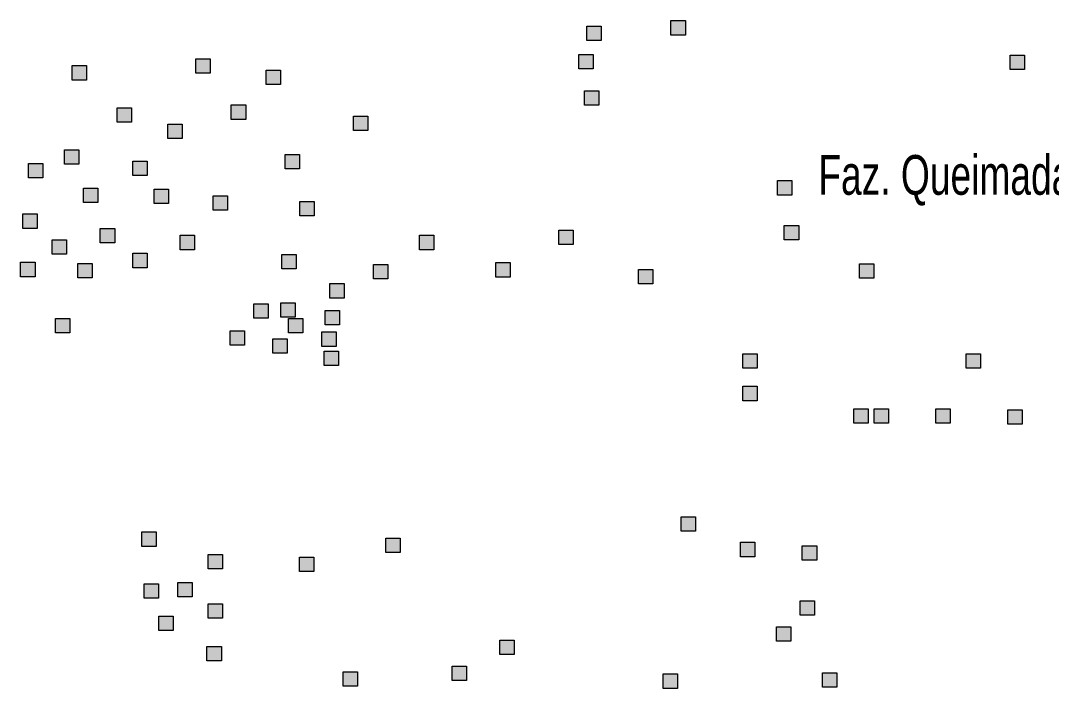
# Model space of a CAD drawing. Extents: x 445.4 to 500, y 8728.7 to 8784.
# Drawn here: x 467.932 to 472.087, y 8728.719 to 8731.409 of the extents above; entities that cross this region are included whole.
import ezdxf

# ---------------------------------------------------------------- set-up
doc = ezdxf.new("R2010")
doc.units = 0
doc.header["$LTSCALE"] = 0.064
doc.layers.add('2', color=7, linetype='Continuous', lineweight=25)
doc.layers.add('61', color=7, linetype='Continuous')

msp = doc.modelspace()

# ---------------------------------------------------------------- hatches: boundary and pattern name
at = {"layer": '2'}
for points in [[(470.5532, 8731.409), (470.6112, 8731.409), (470.6112, 8731.351), (470.5532, 8731.351)], [(470.2138, 8731.3864), (470.2718, 8731.3864), (470.2718, 8731.3284), (470.2138, 8731.3284)], [(470.1821, 8731.2732), (470.2401, 8731.2732), (470.2401, 8731.2152), (470.1821, 8731.2152)], [(468.6377, 8731.2549), (468.6957, 8731.2549), (468.6957, 8731.1969), (468.6377, 8731.1969)], [(471.9206, 8731.2699), (471.9786, 8731.2699), (471.9786, 8731.2119), (471.9206, 8731.2119)], [(468.1399, 8731.2277), (468.1979, 8731.2277), (468.1979, 8731.1697), (468.1399, 8731.1697)], [(468.9214, 8731.2096), (468.9794, 8731.2096), (468.9794, 8731.1516), (468.9214, 8731.1516)], [(470.2047, 8731.1266), (470.2627, 8731.1266), (470.2627, 8731.0686), (470.2047, 8731.0686)], [(468.7811, 8731.0693), (468.8391, 8731.0693), (468.8391, 8731.0113), (468.7811, 8731.0113)], [(468.3209, 8731.0573), (468.3789, 8731.0573), (468.3789, 8730.9993), (468.3209, 8730.9993)], [(469.273, 8731.024), (469.331, 8731.024), (469.331, 8730.966), (469.273, 8730.966)], [(468.5246, 8730.9923), (468.5826, 8730.9923), (468.5826, 8730.9343), (468.5246, 8730.9343)], [(468.1083, 8730.8882), (468.1663, 8730.8882), (468.1663, 8730.8302), (468.1083, 8730.8302)], [(468.9983, 8730.8701), (469.0563, 8730.8701), (469.0563, 8730.8121), (468.9983, 8730.8121)], [(467.9635, 8730.8339), (468.0215, 8730.8339), (468.0215, 8730.7759), (467.9635, 8730.7759)], [(468.3843, 8730.8429), (468.4423, 8730.8429), (468.4423, 8730.7849), (468.3843, 8730.7849)], [(468.1852, 8730.7342), (468.2432, 8730.7342), (468.2432, 8730.6762), (468.1852, 8730.6762)], [(470.983, 8730.7644), (471.041, 8730.7644), (471.041, 8730.7064), (470.983, 8730.7064)], [(468.4703, 8730.7297), (468.5283, 8730.7297), (468.5283, 8730.6717), (468.4703, 8730.6717)], [(468.7075, 8730.7038), (468.7655, 8730.7038), (468.7655, 8730.6458), (468.7075, 8730.6458)], [(469.0571, 8730.6799), (469.1151, 8730.6799), (469.1151, 8730.6219), (469.0571, 8730.6219)], [(467.9408, 8730.6301), (467.9988, 8730.6301), (467.9988, 8730.5721), (467.9408, 8730.5721)], [(468.2531, 8730.5713), (468.3111, 8730.5713), (468.3111, 8730.5133), (468.2531, 8730.5133)], [(471.0102, 8730.5833), (471.0682, 8730.5833), (471.0682, 8730.5253), (471.0102, 8730.5253)], [(468.0585, 8730.526), (468.1165, 8730.526), (468.1165, 8730.468), (468.0585, 8730.468)], [(468.5743, 8730.5441), (468.6323, 8730.5441), (468.6323, 8730.4861), (468.5743, 8730.4861)], [(469.5399, 8730.5441), (469.5979, 8730.5441), (469.5979, 8730.4861), (469.5399, 8730.4861)], [(470.1007, 8730.5652), (470.1587, 8730.5652), (470.1587, 8730.5072), (470.1007, 8730.5072)], [(468.3843, 8730.4717), (468.4423, 8730.4717), (468.4423, 8730.4137), (468.3843, 8730.4137)], [(468.9847, 8730.4671), (469.0427, 8730.4671), (469.0427, 8730.4091), (468.9847, 8730.4091)], [(467.9318, 8730.4354), (467.9898, 8730.4354), (467.9898, 8730.3774), (467.9318, 8730.3774)], [(468.1626, 8730.4309), (468.2206, 8730.4309), (468.2206, 8730.3729), (468.1626, 8730.3729)], [(469.3544, 8730.4264), (469.4124, 8730.4264), (469.4124, 8730.3684), (469.3544, 8730.3684)], [(469.8473, 8730.4339), (469.9053, 8730.4339), (469.9053, 8730.3759), (469.8473, 8730.3759)], [(470.4219, 8730.4067), (470.4799, 8730.4067), (470.4799, 8730.3487), (470.4219, 8730.3487)], [(471.3134, 8730.4293), (471.3714, 8730.4293), (471.3714, 8730.3713), (471.3134, 8730.3713)], [(469.1779, 8730.3494), (469.2359, 8730.3494), (469.2359, 8730.2914), (469.1779, 8730.2914)], [(468.8716, 8730.2679), (468.9296, 8730.2679), (468.9296, 8730.2099), (468.8716, 8730.2099)], [(468.9802, 8730.2724), (469.0382, 8730.2724), (469.0382, 8730.2144), (468.9802, 8730.2144)], [(469.1598, 8730.2408), (469.2178, 8730.2408), (469.2178, 8730.1828), (469.1598, 8730.1828)], [(468.0721, 8730.2091), (468.1301, 8730.2091), (468.1301, 8730.1511), (468.0721, 8730.1511)], [(469.0119, 8730.2091), (469.0699, 8730.2091), (469.0699, 8730.1511), (469.0119, 8730.1511)], [(468.7766, 8730.1593), (468.8346, 8730.1593), (468.8346, 8730.1013), (468.7766, 8730.1013)], [(469.1463, 8730.1547), (469.2043, 8730.1547), (469.2043, 8730.0967), (469.1463, 8730.0967)], [(468.9485, 8730.1276), (469.0065, 8730.1276), (469.0065, 8730.0696), (468.9485, 8730.0696)], [(469.1553, 8730.0778), (469.2133, 8730.0778), (469.2133, 8730.0198), (469.1553, 8730.0198)], [(470.8428, 8730.0671), (470.9008, 8730.0671), (470.9008, 8730.0091), (470.8428, 8730.0091)], [(471.7432, 8730.0671), (471.8012, 8730.0671), (471.8012, 8730.0091), (471.7432, 8730.0091)], [(470.8428, 8729.9358), (470.9008, 8729.9358), (470.9008, 8729.8778), (470.8428, 8729.8778)], [(471.2907, 8729.8453), (471.3487, 8729.8453), (471.3487, 8729.7873), (471.2907, 8729.7873)], [(471.3722, 8729.8453), (471.4302, 8729.8453), (471.4302, 8729.7873), (471.3722, 8729.7873)], [(471.6211, 8729.8453), (471.6791, 8729.8453), (471.6791, 8729.7873), (471.6211, 8729.7873)], [(471.9107, 8729.8408), (471.9687, 8729.8408), (471.9687, 8729.7828), (471.9107, 8729.7828)], [(470.5944, 8729.4099), (470.6524, 8729.4099), (470.6524, 8729.3519), (470.5944, 8729.3519)], [(468.4205, 8729.3488), (468.4785, 8729.3488), (468.4785, 8729.2908), (468.4205, 8729.2908)], [(469.4038, 8729.3246), (469.4618, 8729.3246), (469.4618, 8729.2666), (469.4038, 8729.2666)], [(470.8335, 8729.3073), (470.8915, 8729.3073), (470.8915, 8729.2493), (470.8335, 8729.2493)], [(471.0826, 8729.2929), (471.1406, 8729.2929), (471.1406, 8729.2349), (471.0826, 8729.2349)], [(468.6875, 8729.2583), (468.7455, 8729.2583), (468.7455, 8729.2003), (468.6875, 8729.2003)], [(469.0554, 8729.2477), (469.1134, 8729.2477), (469.1134, 8729.1897), (469.0554, 8729.1897)], [(468.4295, 8729.1406), (468.4875, 8729.1406), (468.4875, 8729.0826), (468.4295, 8729.0826)], [(468.5653, 8729.1451), (468.6233, 8729.1451), (468.6233, 8729.0871), (468.5653, 8729.0871)], [(471.0735, 8729.0711), (471.1315, 8729.0711), (471.1315, 8729.0131), (471.0735, 8729.0131)], [(468.6875, 8729.0591), (468.7455, 8729.0591), (468.7455, 8729.0011), (468.6875, 8729.0011)], [(468.4884, 8729.0093), (468.5464, 8729.0093), (468.5464, 8728.9513), (468.4884, 8728.9513)], [(470.9785, 8728.967), (471.0365, 8728.967), (471.0365, 8728.909), (470.9785, 8728.909)], [(469.8637, 8728.9126), (469.9217, 8728.9126), (469.9217, 8728.8546), (469.8637, 8728.8546)], [(468.6829, 8728.8871), (468.7409, 8728.8871), (468.7409, 8728.8291), (468.6829, 8728.8291)], [(469.2319, 8728.7859), (469.2899, 8728.7859), (469.2899, 8728.7279), (469.2319, 8728.7279)], [(469.6708, 8728.8085), (469.7288, 8728.8085), (469.7288, 8728.7505), (469.6708, 8728.7505)], [(471.164, 8728.7813), (471.222, 8728.7813), (471.222, 8728.7233), (471.164, 8728.7233)], [(470.5215, 8728.7768), (470.5795, 8728.7768), (470.5795, 8728.7188), (470.5215, 8728.7188)]]:
    msp.add_hatch(color=256, dxfattribs=at).paths.add_polyline_path(points)

# ---------------------------------------------------------------- linework, layer by layer
for points in [[(470.5532, 8731.409), (470.6112, 8731.409), (470.6112, 8731.351), (470.5532, 8731.351)], [(470.2138, 8731.3864), (470.2718, 8731.3864), (470.2718, 8731.3284), (470.2138, 8731.3284)], [(470.1821, 8731.2732), (470.2401, 8731.2732), (470.2401, 8731.2152), (470.1821, 8731.2152)], [(468.6377, 8731.2549), (468.6957, 8731.2549), (468.6957, 8731.1969), (468.6377, 8731.1969)], [(471.9206, 8731.2699), (471.9786, 8731.2699), (471.9786, 8731.2119), (471.9206, 8731.2119)], [(468.1399, 8731.2277), (468.1979, 8731.2277), (468.1979, 8731.1697), (468.1399, 8731.1697)], [(468.9214, 8731.2096), (468.9794, 8731.2096), (468.9794, 8731.1516), (468.9214, 8731.1516)], [(470.2047, 8731.1266), (470.2627, 8731.1266), (470.2627, 8731.0686), (470.2047, 8731.0686)], [(468.7811, 8731.0693), (468.8391, 8731.0693), (468.8391, 8731.0113), (468.7811, 8731.0113)], [(468.3209, 8731.0573), (468.3789, 8731.0573), (468.3789, 8730.9993), (468.3209, 8730.9993)], [(469.273, 8731.024), (469.331, 8731.024), (469.331, 8730.966), (469.273, 8730.966)], [(468.5246, 8730.9923), (468.5826, 8730.9923), (468.5826, 8730.9343), (468.5246, 8730.9343)], [(468.1083, 8730.8882), (468.1663, 8730.8882), (468.1663, 8730.8302), (468.1083, 8730.8302)], [(468.9983, 8730.8701), (469.0563, 8730.8701), (469.0563, 8730.8121), (468.9983, 8730.8121)], [(467.9635, 8730.8339), (468.0215, 8730.8339), (468.0215, 8730.7759), (467.9635, 8730.7759)], [(468.3843, 8730.8429), (468.4423, 8730.8429), (468.4423, 8730.7849), (468.3843, 8730.7849)], [(468.1852, 8730.7342), (468.2432, 8730.7342), (468.2432, 8730.6762), (468.1852, 8730.6762)], [(470.983, 8730.7644), (471.041, 8730.7644), (471.041, 8730.7064), (470.983, 8730.7064)], [(468.4703, 8730.7297), (468.5283, 8730.7297), (468.5283, 8730.6717), (468.4703, 8730.6717)], [(468.7075, 8730.7038), (468.7655, 8730.7038), (468.7655, 8730.6458), (468.7075, 8730.6458)], [(469.0571, 8730.6799), (469.1151, 8730.6799), (469.1151, 8730.6219), (469.0571, 8730.6219)], [(467.9408, 8730.6301), (467.9988, 8730.6301), (467.9988, 8730.5721), (467.9408, 8730.5721)], [(468.2531, 8730.5713), (468.3111, 8730.5713), (468.3111, 8730.5133), (468.2531, 8730.5133)], [(471.0102, 8730.5833), (471.0682, 8730.5833), (471.0682, 8730.5253), (471.0102, 8730.5253)], [(468.0585, 8730.526), (468.1165, 8730.526), (468.1165, 8730.468), (468.0585, 8730.468)], [(468.5743, 8730.5441), (468.6323, 8730.5441), (468.6323, 8730.4861), (468.5743, 8730.4861)], [(469.5399, 8730.5441), (469.5979, 8730.5441), (469.5979, 8730.4861), (469.5399, 8730.4861)], [(470.1007, 8730.5652), (470.1587, 8730.5652), (470.1587, 8730.5072), (470.1007, 8730.5072)], [(468.3843, 8730.4717), (468.4423, 8730.4717), (468.4423, 8730.4137), (468.3843, 8730.4137)], [(468.9847, 8730.4671), (469.0427, 8730.4671), (469.0427, 8730.4091), (468.9847, 8730.4091)], [(467.9318, 8730.4354), (467.9898, 8730.4354), (467.9898, 8730.3774), (467.9318, 8730.3774)], [(468.1626, 8730.4309), (468.2206, 8730.4309), (468.2206, 8730.3729), (468.1626, 8730.3729)], [(469.3544, 8730.4264), (469.4124, 8730.4264), (469.4124, 8730.3684), (469.3544, 8730.3684)], [(469.8473, 8730.4339), (469.9053, 8730.4339), (469.9053, 8730.3759), (469.8473, 8730.3759)], [(470.4219, 8730.4067), (470.4799, 8730.4067), (470.4799, 8730.3487), (470.4219, 8730.3487)], [(471.3134, 8730.4293), (471.3714, 8730.4293), (471.3714, 8730.3713), (471.3134, 8730.3713)], [(469.1779, 8730.3494), (469.2359, 8730.3494), (469.2359, 8730.2914), (469.1779, 8730.2914)], [(468.8716, 8730.2679), (468.9296, 8730.2679), (468.9296, 8730.2099), (468.8716, 8730.2099)], [(468.9802, 8730.2724), (469.0382, 8730.2724), (469.0382, 8730.2144), (468.9802, 8730.2144)], [(469.1598, 8730.2408), (469.2178, 8730.2408), (469.2178, 8730.1828), (469.1598, 8730.1828)], [(468.0721, 8730.2091), (468.1301, 8730.2091), (468.1301, 8730.1511), (468.0721, 8730.1511)], [(469.0119, 8730.2091), (469.0699, 8730.2091), (469.0699, 8730.1511), (469.0119, 8730.1511)], [(468.7766, 8730.1593), (468.8346, 8730.1593), (468.8346, 8730.1013), (468.7766, 8730.1013)], [(469.1463, 8730.1547), (469.2043, 8730.1547), (469.2043, 8730.0967), (469.1463, 8730.0967)], [(468.9485, 8730.1276), (469.0065, 8730.1276), (469.0065, 8730.0696), (468.9485, 8730.0696)], [(469.1553, 8730.0778), (469.2133, 8730.0778), (469.2133, 8730.0198), (469.1553, 8730.0198)], [(470.8428, 8730.0671), (470.9008, 8730.0671), (470.9008, 8730.0091), (470.8428, 8730.0091)], [(471.7432, 8730.0671), (471.8012, 8730.0671), (471.8012, 8730.0091), (471.7432, 8730.0091)], [(470.8428, 8729.9358), (470.9008, 8729.9358), (470.9008, 8729.8778), (470.8428, 8729.8778)], [(471.2907, 8729.8453), (471.3487, 8729.8453), (471.3487, 8729.7873), (471.2907, 8729.7873)], [(471.3722, 8729.8453), (471.4302, 8729.8453), (471.4302, 8729.7873), (471.3722, 8729.7873)], [(471.6211, 8729.8453), (471.6791, 8729.8453), (471.6791, 8729.7873), (471.6211, 8729.7873)], [(471.9107, 8729.8408), (471.9687, 8729.8408), (471.9687, 8729.7828), (471.9107, 8729.7828)], [(470.5944, 8729.4099), (470.6524, 8729.4099), (470.6524, 8729.3519), (470.5944, 8729.3519)], [(468.4205, 8729.3488), (468.4785, 8729.3488), (468.4785, 8729.2908), (468.4205, 8729.2908)], [(469.4038, 8729.3246), (469.4618, 8729.3246), (469.4618, 8729.2666), (469.4038, 8729.2666)], [(470.8335, 8729.3073), (470.8915, 8729.3073), (470.8915, 8729.2493), (470.8335, 8729.2493)], [(471.0826, 8729.2929), (471.1406, 8729.2929), (471.1406, 8729.2349), (471.0826, 8729.2349)], [(468.6875, 8729.2583), (468.7455, 8729.2583), (468.7455, 8729.2003), (468.6875, 8729.2003)], [(469.0554, 8729.2477), (469.1134, 8729.2477), (469.1134, 8729.1897), (469.0554, 8729.1897)], [(468.4295, 8729.1406), (468.4875, 8729.1406), (468.4875, 8729.0826), (468.4295, 8729.0826)], [(468.5653, 8729.1451), (468.6233, 8729.1451), (468.6233, 8729.0871), (468.5653, 8729.0871)], [(471.0735, 8729.0711), (471.1315, 8729.0711), (471.1315, 8729.0131), (471.0735, 8729.0131)], [(468.6875, 8729.0591), (468.7455, 8729.0591), (468.7455, 8729.0011), (468.6875, 8729.0011)], [(468.4884, 8729.0093), (468.5464, 8729.0093), (468.5464, 8728.9513), (468.4884, 8728.9513)], [(470.9785, 8728.967), (471.0365, 8728.967), (471.0365, 8728.909), (470.9785, 8728.909)], [(469.8637, 8728.9126), (469.9217, 8728.9126), (469.9217, 8728.8546), (469.8637, 8728.8546)], [(468.6829, 8728.8871), (468.7409, 8728.8871), (468.7409, 8728.8291), (468.6829, 8728.8291)], [(469.2319, 8728.7859), (469.2899, 8728.7859), (469.2899, 8728.7279), (469.2319, 8728.7279)], [(469.6708, 8728.8085), (469.7288, 8728.8085), (469.7288, 8728.7505), (469.6708, 8728.7505)], [(471.164, 8728.7813), (471.222, 8728.7813), (471.222, 8728.7233), (471.164, 8728.7233)], [(470.5215, 8728.7768), (470.5795, 8728.7768), (470.5795, 8728.7188), (470.5215, 8728.7188)]]:
    msp.add_lwpolyline(points, close=True, dxfattribs=at)

# ---------------------------------------------------------------- texts
at = {"layer": '61', "width": 0.7}
msp.add_text('Faz. Queimada dos Porcos', height=0.16, dxfattribs=at).set_placement((471.1473, 8730.7075))

doc.saveas('drawing.dxf')
